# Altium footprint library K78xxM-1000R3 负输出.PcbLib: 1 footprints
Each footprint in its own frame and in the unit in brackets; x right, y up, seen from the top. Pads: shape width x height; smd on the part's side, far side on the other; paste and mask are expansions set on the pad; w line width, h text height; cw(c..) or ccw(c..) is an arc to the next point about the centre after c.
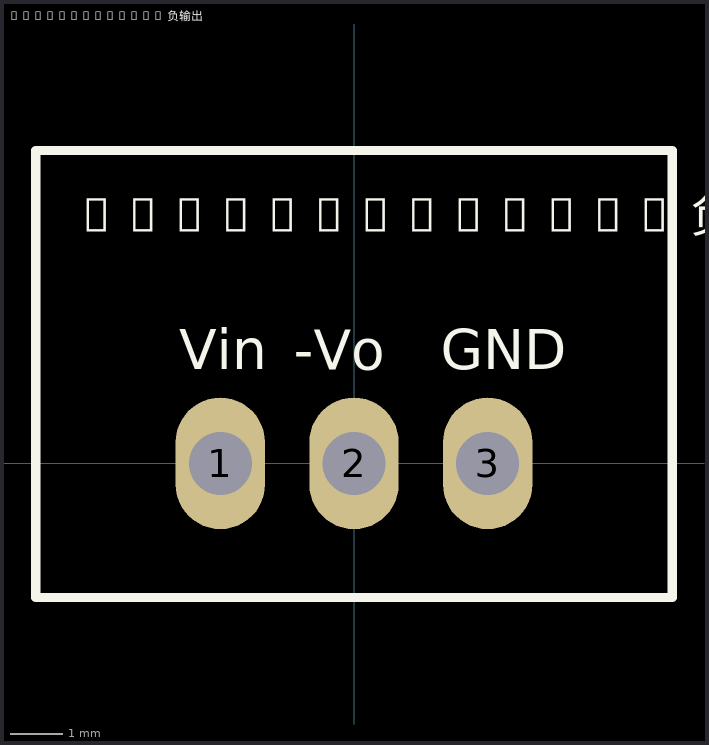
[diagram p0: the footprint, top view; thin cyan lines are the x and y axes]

## K78xxM-1000R3 负输出 [mm]
pads (3):
  oval 1.7x2.5 hole 1.2: 1(-2.54,0) 2(0,0) 3(2.54,0)
Top Overlay:
  lines w0.178: -6.05,-2.55 6.05,-2.55 6.05,5.95 -6.05,5.95 -6.05,-2.55
  text "K78xxM-1000R3 负输出" at -5.334,4.191 h1.1
  text "-Vo" at -1.143,1.778 h0.76
  text "Vin" at -3.322,1.79 h0.76
  text "GND" at 1.651,1.79 h0.76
